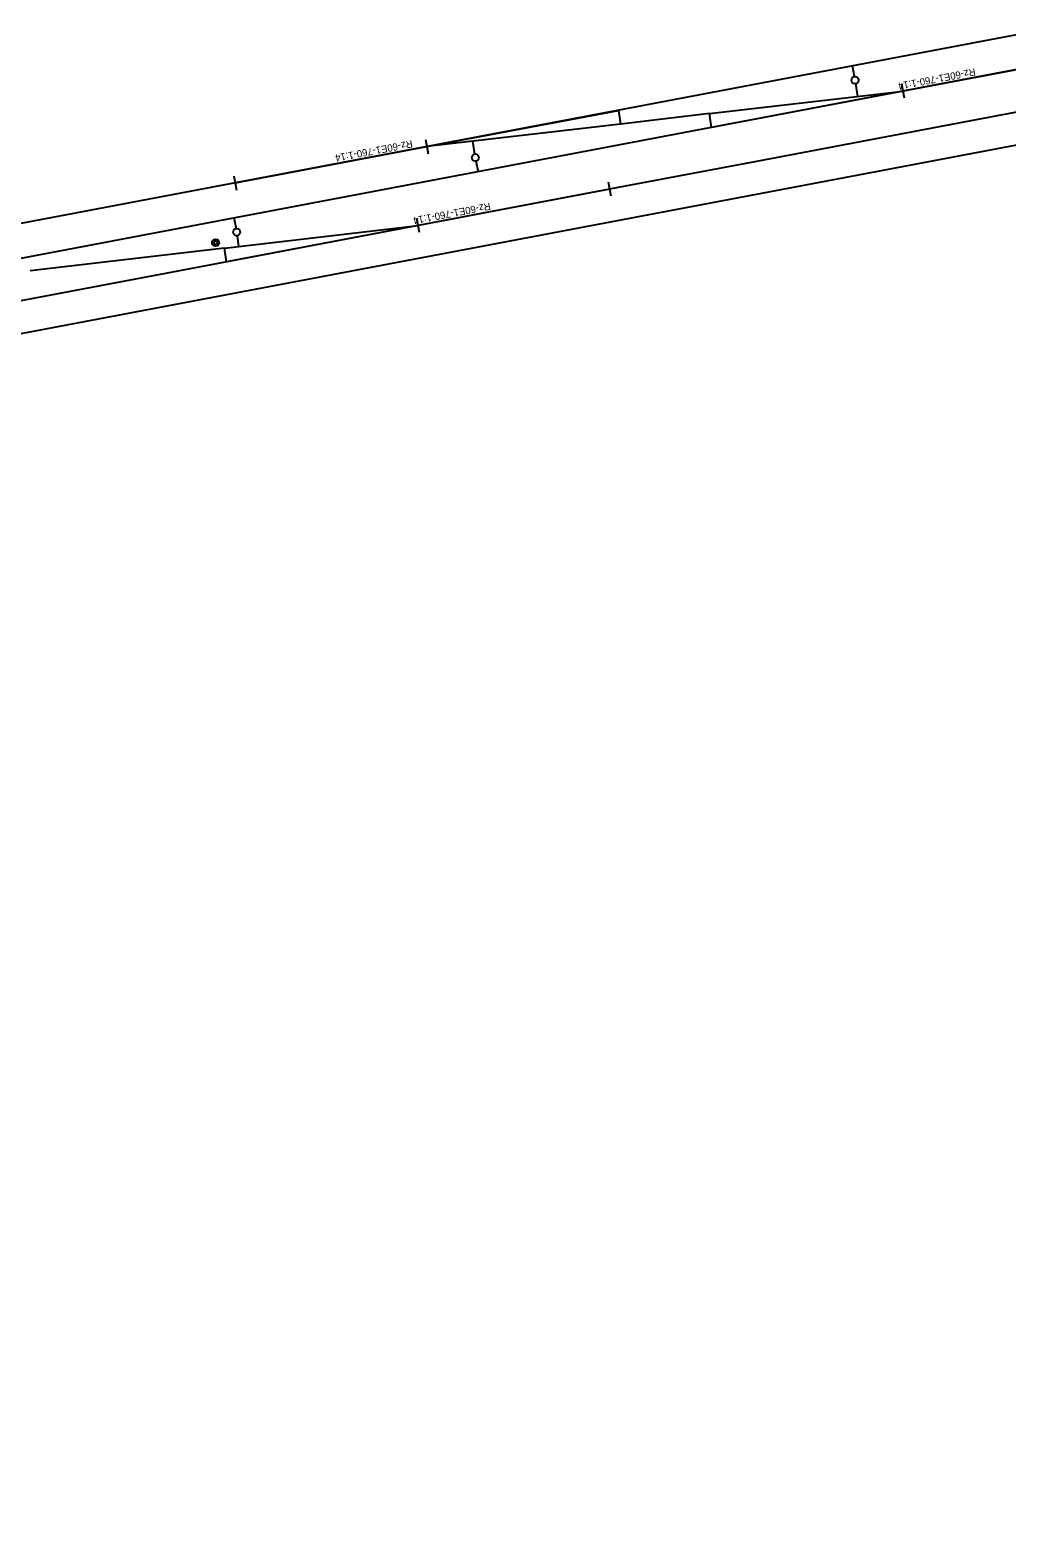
# Model space of a CAD drawing. Extents: x 6540402 to 6566579, y 5525343 to 5532423.
# Drawn here: x 6556823.1 to 6556958.8, y 5528387.9 to 5528597.5 of the extents above; entities that cross this region are included whole.
import ezdxf

# ---------------------------------------------------------------- set-up
doc = ezdxf.new("R2010")
doc.units = 0
for name, color, linetype in [('TOR_PS_ODW-studnie betonowe', 7, 'Continuous'), ('TOR_PS_OPIS_T-opisy dodatkowe', 7, 'Continuous'), ('TOR_PS_OPIS_T-ukresy', 7, 'Continuous'), ('TOR_PS_T-rozjazdy projektowane', 7, 'Continuous'), ('TOR_PS_T-tory projektowane', 7, 'Continuous')]:
    doc.layers.add(name, color=color, linetype=linetype)

msp = doc.modelspace()

# ---------------------------------------------------------------- linework, layer by layer
at = {"layer": 'TOR_PS_ODW-studnie betonowe'}
for radius in [0.5, 0.25]:
    msp.add_circle((6556848.84, 5528567.95), radius, dxfattribs=at)
at = {"layer": 'TOR_PS_OPIS_T-ukresy'}
for p, q in [((6556937.63, 5528591.03), (6556937.35, 5528592.51)), ((6556937.79, 5528590.05), (6556938.05, 5528588.27)), ((6556884.86, 5528580.27), (6556884.61, 5528582.04)), ((6556885.03, 5528579.28), (6556885.31, 5528577.81)), ((6556851.39, 5528571.38), (6556851.67, 5528569.91)), ((6556851.82, 5528568.92), (6556852, 5528567.42))]:
    msp.add_line(p, q, dxfattribs=at)
for centre in [(6556937.72, 5528590.54), (6556884.94, 5528579.78), (6556851.76, 5528569.42)]:
    msp.add_circle(centre, 0.5, dxfattribs=at)
at = {"layer": 'TOR_PS_T-rozjazdy projektowane'}
for p, q in [((6556971.05, 5528594.06), (6556944.41, 5528589.01)), ((6556944.6, 5528588.03), (6556944.23, 5528590)), ((6556851.56, 5528576.25), (6556878.19, 5528581.3)), ((6556878.01, 5528582.28), (6556878.38, 5528580.31)), ((6556851.37, 5528577.23), (6556851.74, 5528575.26)), ((6556903.62, 5528575.38), (6556876.99, 5528570.33)), ((6556903.81, 5528574.4), (6556903.44, 5528576.36)), ((6556877.17, 5528569.35), (6556876.8, 5528571.31))]:
    msp.add_line(p, q, dxfattribs=at)
for points in [[(6556944.41, 5528589.01), (6556917.78, 5528583.97), (6556917.49, 5528585.88)], [(6556944.41, 5528589.01), (6556917.78, 5528583.97), (6556917.49, 5528585.88)], [(6556878.19, 5528581.3), (6556904.83, 5528586.34), (6556905.12, 5528584.43)], [(6556878.19, 5528581.3), (6556904.83, 5528586.34), (6556905.12, 5528584.43)], [(6556876.99, 5528570.33), (6556850.35, 5528565.28), (6556850.06, 5528567.19)], [(6556876.99, 5528570.33), (6556850.35, 5528565.28), (6556850.06, 5528567.19)]]:
    msp.add_lwpolyline(points, close=True, dxfattribs=at)
at = {"layer": 'TOR_PS_T-tory projektowane'}
for p, q in [((6557664.82, 5528730.4), (6555967.41, 5528408.66)), ((6557450.25, 5528674.41), (6556612.98, 5528515.71)), ((6556971.05, 5528594.06), (6556930.18, 5528586.32)), ((6556930.18, 5528586.32), (6555917.77, 5528394.41)), ((6556917.49, 5528585.88), (6556905.17, 5528584.44)), ((6556964.14, 5528586.85), (6556923.27, 5528579.1)), ((6556923.27, 5528579.1), (6556906.51, 5528575.93)), ((6556906.51, 5528575.93), (6556842.83, 5528563.85)), ((6556850.06, 5528567.19), (6556823.05, 5528564.04)), ((6556842.83, 5528563.85), (6554354.28, 5528092.14))]:
    msp.add_line(p, q, dxfattribs=at)

# ---------------------------------------------------------------- texts
at = {"layer": 'TOR_PS_OPIS_T-opisy dodatkowe'}
msp.add_text('km 62+427(istn.) = km 62+427(proj.)', height=35, rotation=101.1578, dxfattribs=at).set_placement((6556868.89, 5527786.38))
at = {"layer": 'TOR_PS_T-rozjazdy projektowane'}
for p in [(6556954.37, 5528592.2), (6556876.12, 5528582.2), (6556886.95, 5528573.51)]:
    msp.add_text('Rz-60E1-760-1:14', height=1, rotation=190.7332, dxfattribs=at).set_placement(p)

doc.saveas('drawing.dxf')
